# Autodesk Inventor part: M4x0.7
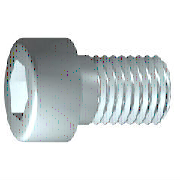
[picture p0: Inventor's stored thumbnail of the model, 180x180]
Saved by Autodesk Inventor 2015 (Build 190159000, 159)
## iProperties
IsCustomPart: 1
Created: 2015-10
Part Number: M4x0.7
Material: Steel, Mild
Description: 6각머리 태핑 나사
Document SubType Name: Modeling
Standard: KS B 1003
Designer: mdu
Standards Organization: KS
Language: ko-KR
Size Designation: M 4 x 16
Categories: <MemberInstance><Categories><Category DisplayName="조임쇠" InternalName="e4da775c-781d-43d5-af7c-5136215cf5a6" Mnemonic="FSTN"><Category DisplayName="볼트" InternalN
Density: 7.85 g/cm^3
Mass: 2.62639 g
Surface Area: 3.81118 cm^2
Volume: 0.334572 cm^3
Appearance: Steel
Author: mdu
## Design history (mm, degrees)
revolve "본체" stored, may be unused: angle "d10" = 90 deg
sketch "스케치2"
  geometry: L1 (0, -4.9)-(0, 4.9) reference; L2 (-4.9, 0)-(4.9, 0) reference; L3 (1.732, 0)-(0.866, -1.5); L4 (0.866, -1.5)-(-0.866, -1.5); L5 (-0.866, -1.5)-(-1.732, 0); L6 (-1.732, 0)-(-0.866, 1.5); L7 (-0.866, 1.5)-(0.866, 1.5); L8 (0.866, 1.5)-(1.732, 0); 2 further points
  constraints: 12 end point, 1 coincident, 1 horizontal alignment, 1 point on line, 12 other
extrude "슬롯" join sketch "스케치2" stored distance "d11" = 10; taper "d12" = 0 deg
workplane "Work Plane1"
fillet "Fillet2" dims "d30" = 0.1 (= R)
body "Solid1"
fillet "모깎기1" dims "d17" = 0.4 (= RR)
feature "스레드" dims "d13" = 14.25 (= GEL), "d14" = 0
chamfer "모따기1" distance "d15" = 0.42941 (= -0.5 x SPD + 0.5 x GD); stored, may be unused: second distance "d16" = 0.42941 (= GUL), angle "d27" = 45 deg
sketch "스케치1"
  geometry: L1 (-1, 0)-(16, 0); L2 (16, 0)-(16, 2); L3 (16, 2)-(1.75, 2); L4 (1.75, 2)-(1.32, 2); L5 (1.32, 2)-(0, 2); L6 (0, 2)-(0, 3.5); L7 (0, 3.5)-(-4, 3.5); L8 (-4, 3.5)-(-4, 1.732); L9 (-4, 1.732)-(-2, 1.732); L10 (-2, 1.732)-(-1, 0); L11 (-8, 0)-(20, 0) reference; L12 (0, -0.7)-(0, 4.2) reference; L13 (1.75, 2)-(0, 2)
  constraints: 22 end point, 6 parallel, 2 collinear, 2 perpendicular, 1 horizontal, 1 point on line
  dimensions: "d1" = 14.25 distance from line of L3.end L2 (= GEL); "d2" = 0.42952 distance of L4.end L3.end (computed from GAL); "d3" = 4 distance between parallel lines of L8 L6 (= KOH); "d4" = 2 distance of L8.end L9.end (= INTI); "d5" = 60 deg angle of L10 L1; "d6" = 4 diameter of L3 L1 (= GD); "d7" = 4 diameter of L5 L1 (= BDM); "d8" = 3.4641 diameter of L9 L1 (= 1.1547 x SW); "d9" = 7 diameter of L7 L1 (= KOD); "d26" = 16 distance between parallel lines of L12 L2 (= NLG)
other parameters: "GD" = 4 (= NND) [user parameter; used in 2 equation terms], "NLG" = 16 [user parameter; used in 1 equation term], "GEL" = 14.25 [user parameter; used in 2 equation terms], "KOD" = 7 [user parameter; used in 1 equation term], "KOH" = 4 [user parameter; used in 1 equation term], "INTI" = 2 [user parameter; used in 1 equation term], "GAL" = 0.42941 (= 0.61345 x PTC) [user parameter; used in 1 equation term], "GUL" = 0.42941 (= 0.61345 x PTC) [user parameter; used in 1 equation term], "BDM" = 4 (= NND) [user parameter; used in 1 equation term], "SW" = 3 [user parameter; used in 2 equation terms], "RR" = 0.4 [user parameter; used in 1 equation term], "SPD" = 3.14117 (= NND - 1.2269 x PTC) [user parameter; used in 1 equation term], "d19" = 0, "d28" = 0, "d29" = 0, "R" = 0.1 [user parameter; used in 1 equation term], "PHH" = 0.2 [user parameter], "GD1" = 3.14117 (= THREADDIA - 1.2269 x PTC) [user parameter], "THREADDIA" = 4 [user parameter; used in 1 equation term], "FAWI" = 45 deg [user parameter], "TPU" = 14.28571 (computed from PTC) [user parameter], "PTC" = 0.7 [user parameter; used in 5 equation terms], "NND" = 4 [user parameter; used in 3 equation terms], "TOA" = 30 deg [user parameter], "E0" = 3.465 (= 1.155 x SW) [user parameter]
